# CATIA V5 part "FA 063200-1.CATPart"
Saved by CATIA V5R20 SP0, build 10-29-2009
Part number: FA 063200-1
Revision: ANY
Definition: UNKNOWN
Nomenclature: FA 063200-1
Source: Unknown
Bounding box of the stored display mesh (mm): x -2.5 to 2.5, y 0.15 to 2.5, z -2.5 to 2.5
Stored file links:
  C:\Users\Utente\Desktop\IO LAVORO\3D X SITO CF\CUMSA\3D files FA\FA 0632SF\FA 063200-1.CATPart

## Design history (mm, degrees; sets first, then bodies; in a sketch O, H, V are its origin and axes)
Body1 "Cortar-Extruir1" (main body)
  Solid1: solid without history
